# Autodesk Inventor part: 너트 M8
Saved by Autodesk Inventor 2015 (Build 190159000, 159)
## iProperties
Created: 2025-08
Part Number: 너트 M8
Material: 일반
Document SubType Name: Modeling
Designer: user
Density: 1 g/cm^3
Appearance: 기본값
Author: jhkim
Description: 플랜지붙이 6각 너트 - 일반 스레드
Creation Date: 2025-08-05
Sending System: Autodesk Inventor 2026
Preprocessor: ST-DEVELOPER v20.1
Author: user
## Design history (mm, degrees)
node "너트 M81"
body "Solid1"
node "기준1"
